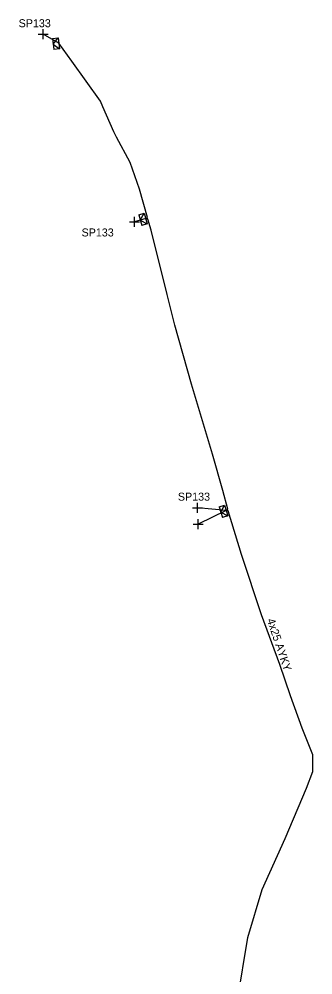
# Model space of a CAD drawing. Extents: x -763093 to -760976, y -1155572 to -1152009.
# Drawn here: x -763092.9 to -763056.2, y -1154111.9 to -1153992.5 of the extents above; entities that cross this region are included whole.
import ezdxf

# ---------------------------------------------------------------- set-up
doc = ezdxf.new("R2010")
doc.units = 0
for name, color, linetype in [('Vrstva 1', 7, 'Continuous'), ('Vrstva 31', 7, 'Continuous'), ('Vrstva 33', 7, 'Continuous'), ('Vrstva 34', 7, 'Continuous'), ('Vrstva 5', 7, 'Continuous'), ('Vrstva 59', 7, 'Continuous'), ('Vrstva 6', 7, 'Continuous'), ('Vrstva 9', 7, 'Continuous')]:
    doc.layers.add(name, color=color, linetype=linetype)

# ---------------------------------------------------------------- blocks, each defined once
blk = doc.blocks.new('NN800')
at = {"layer": 'Vrstva 1'}
for points in [[(-0.44, 0.44), (0.44, -0.44)], [(-0.44, -0.44), (0.44, 0.44)]]:
    blk.add_lwpolyline(points, dxfattribs=at)
blk = doc.blocks.new('NN630')
at = {"layer": 'Vrstva 9'}
for points in [[(0, -0.7), (-0.7, 0)], [(-0.7, -0.7), (-0.7, 0), (0.7, 0), (0.7, -0.7)], [(-0.7, -0.7), (0.7, -0.7)], [(0, -0.7), (0.7, 0)]]:
    blk.add_lwpolyline(points, dxfattribs=at)

msp = doc.modelspace()

# ---------------------------------------------------------------- linework, layer by layer
at = {"layer": 'Vrstva 5'}
msp.add_lwpolyline([(-763065.63, -1154115.07), (-763064.32, -1154107.23), (-763062.54, -1154101.26), (-763059.68, -1154094.86), (-763056.99, -1154088.56), (-763056.23, -1154086.48), (-763056.21, -1154084.4), (-763057.56, -1154081.08), (-763059, -1154077.03), (-763060.33, -1154073.13), (-763062.64, -1154066.91), (-763065.12, -1154059.39), (-763066.77, -1154053.94), (-763067.04, -1154053.89), (-763066.83, -1154053.74), (-763067.46, -1154051.37), (-763068.74, -1154046.85), (-763071.36, -1154038.09), (-763073.44, -1154030.73), (-763074.39, -1154026.92), (-763076.4, -1154018.86), (-763076.81, -1154017.47), (-763077.09, -1154017.42), (-763076.87, -1154017.27), (-763077.88, -1154013.75), (-763079.05, -1154010.4), (-763080.75, -1154007.24), (-763081.09, -1154006.58), (-763082.43, -1154003.46), (-763082.74, -1154002.75), (-763086.32, -1153997.75), (-763087.94, -1153995.52)], dxfattribs=at)
at = {"layer": 'Vrstva 59'}
for points in [[(-763087.94, -1153995.52), (-763089.91, -1153994.37)], [(-763077.09, -1154017.42), (-763078.48, -1154017.84)], [(-763067.04, -1154053.89), (-763070.63, -1154053.54)], [(-763067.04, -1154053.89), (-763070.54, -1154055.61)]]:
    msp.add_lwpolyline(points, dxfattribs=at)

# ---------------------------------------------------------------- block references
at = {"layer": 'Vrstva 31'}
for p, rotation in [((-763087.94, -1153995.52), -82.89566389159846), ((-763077.09, -1154017.42), -74.0058480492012), ((-763067.04, -1154053.89), -72.41965831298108)]:
    msp.add_blockref('NN630', p, dxfattribs=dict(at, rotation=rotation))
at = {"layer": 'Vrstva 34'}
for p, rotation in [((-763089.91, -1153994.37), 45), ((-763078.48, -1154017.84), 45), ((-763070.63, -1154053.54), 44.99999995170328), ((-763070.54, -1154055.61), 45)]:
    msp.add_blockref('NN800', p, dxfattribs=dict(at, rotation=rotation))

# ---------------------------------------------------------------- texts
at = {"layer": 'Vrstva 33'}
for p in [(-763092.96, -1153993.51), (-763085.1, -1154019.65), (-763073.07, -1154052.66)]:
    msp.add_text('SP133', height=1, dxfattribs=at).set_placement(p)
at = {"layer": 'Vrstva 6'}
msp.add_text('4x25 AYKY', height=1, rotation=288.626, dxfattribs=at).set_placement((-763061.97, -1154067.56))

doc.saveas('drawing.dxf')
